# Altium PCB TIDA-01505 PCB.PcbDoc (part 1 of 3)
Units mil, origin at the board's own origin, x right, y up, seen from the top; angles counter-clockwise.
Board outline 7874.02 x 6929.13 mil, 2 copper layers (Top Layer, Bottom Layer), stack 62 mil thick; 307 components, 129 nets, 623 pads, 701 vias.
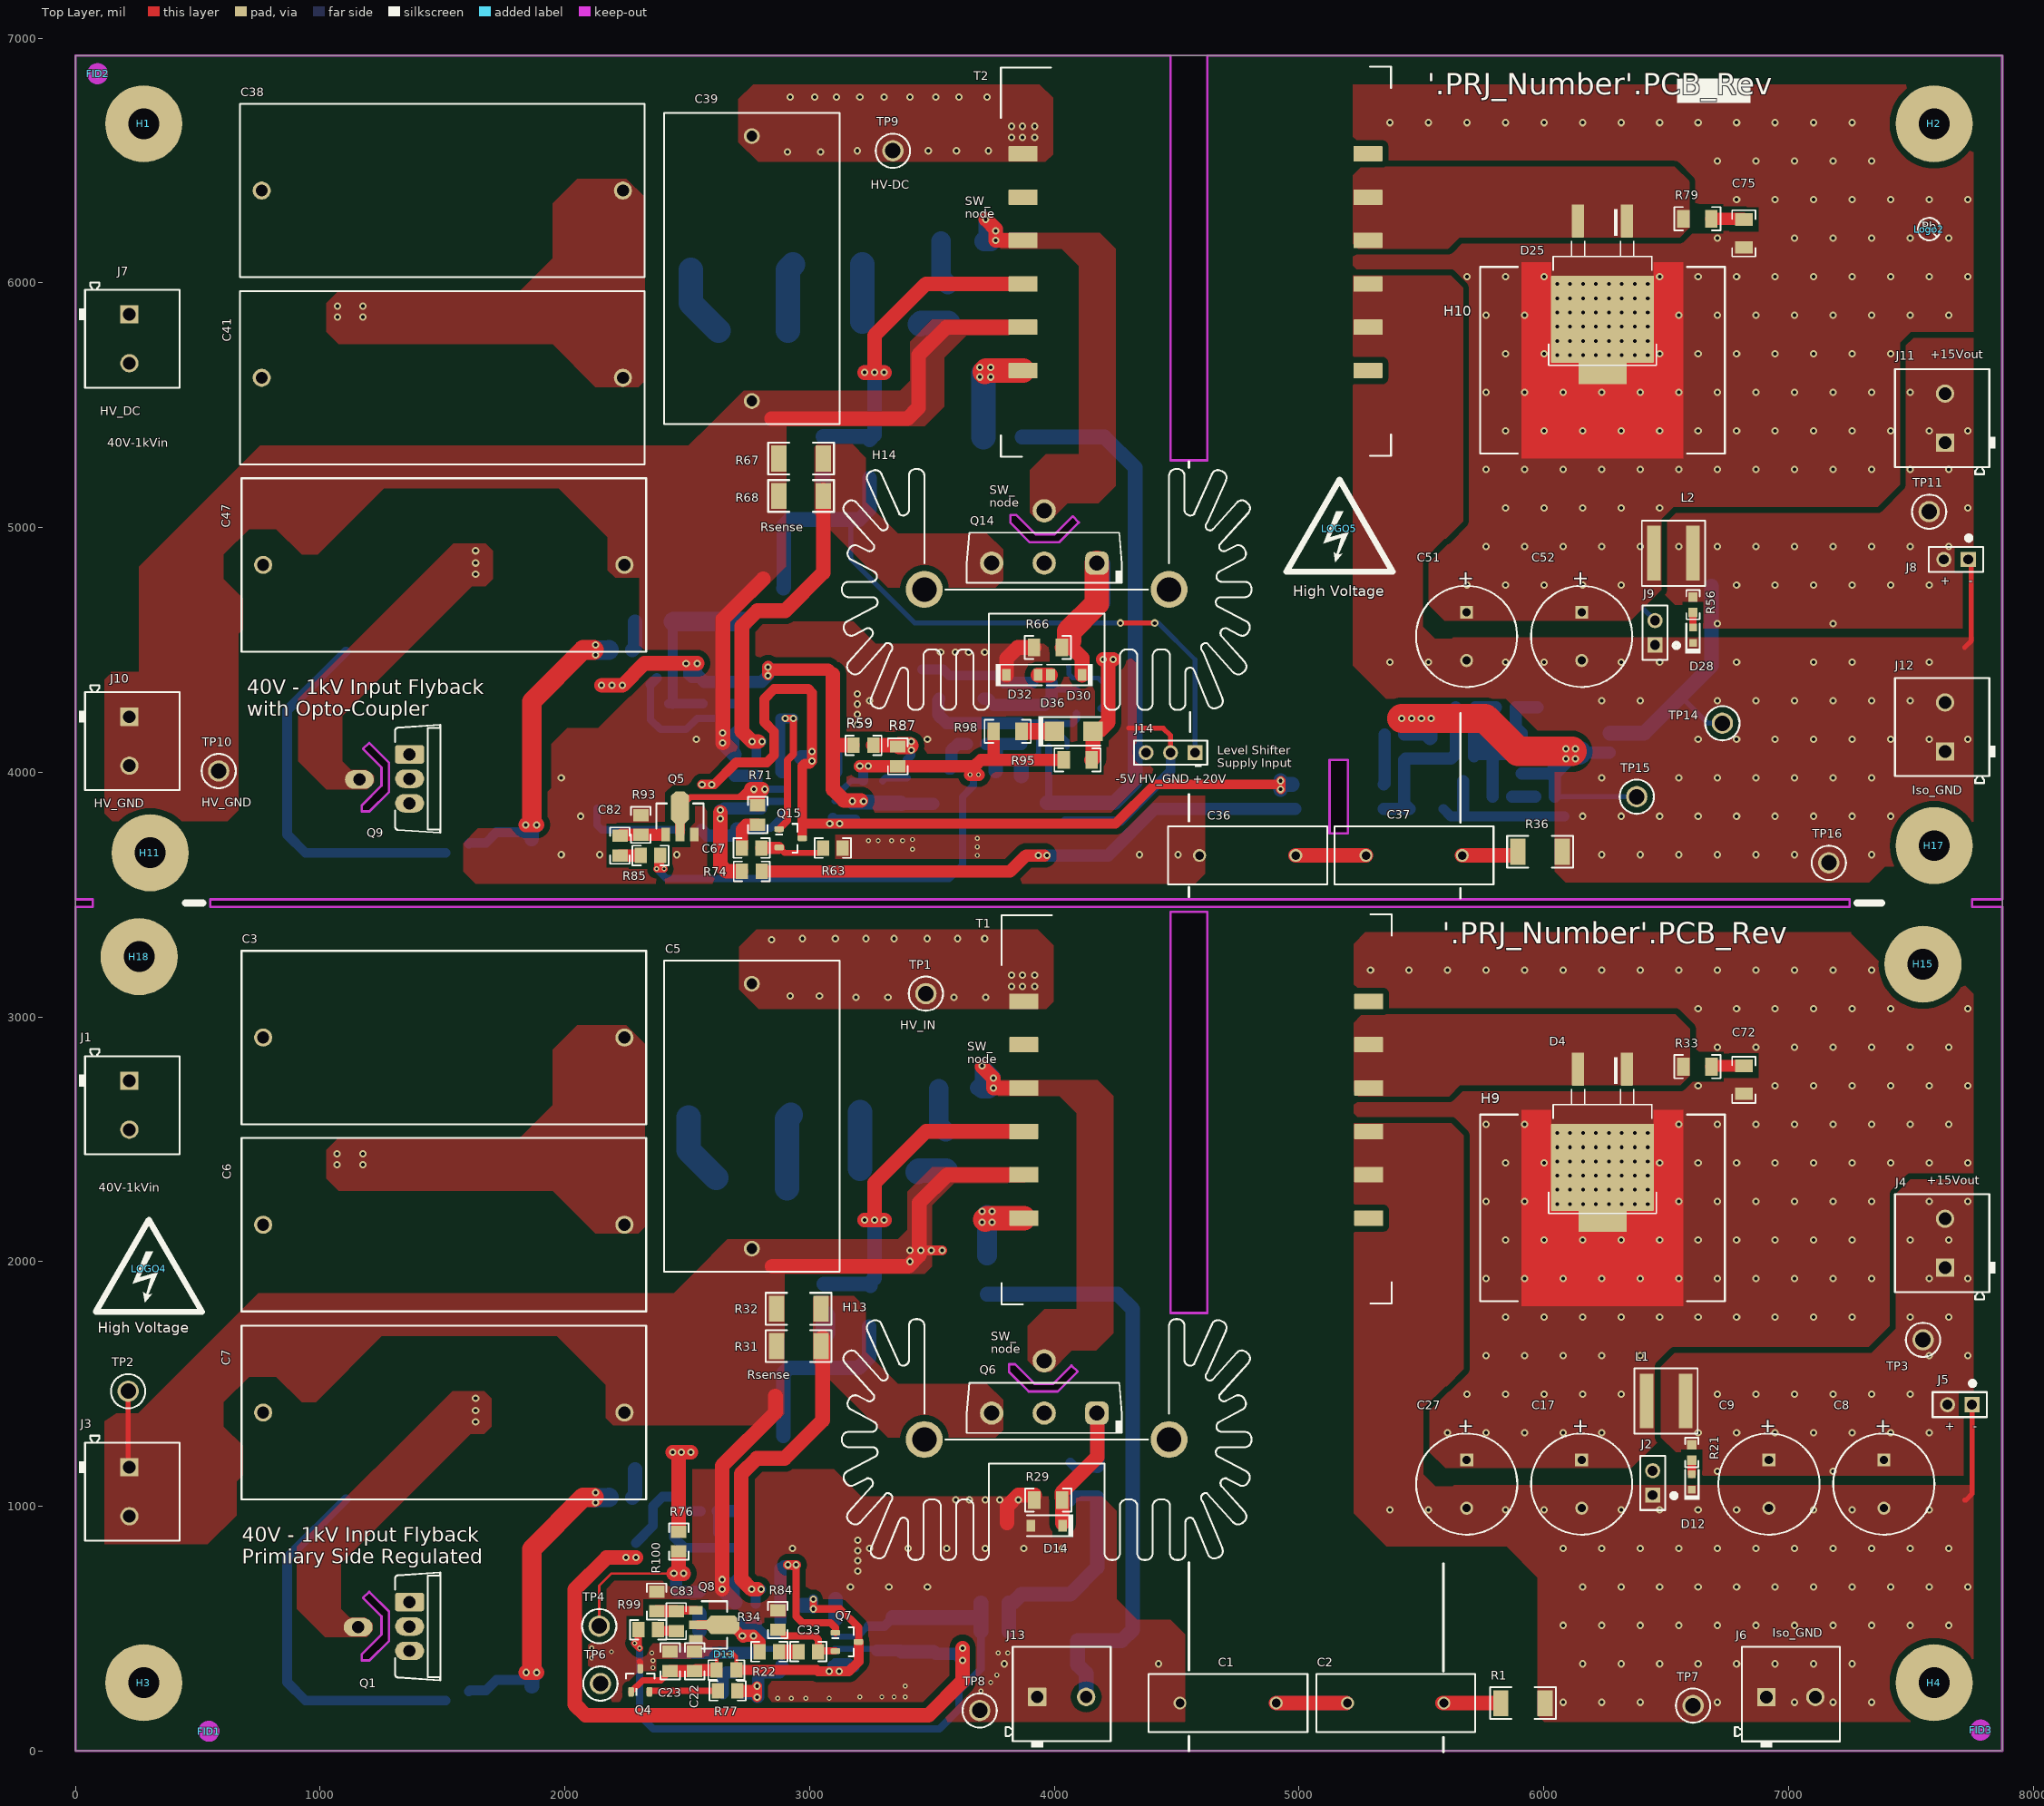
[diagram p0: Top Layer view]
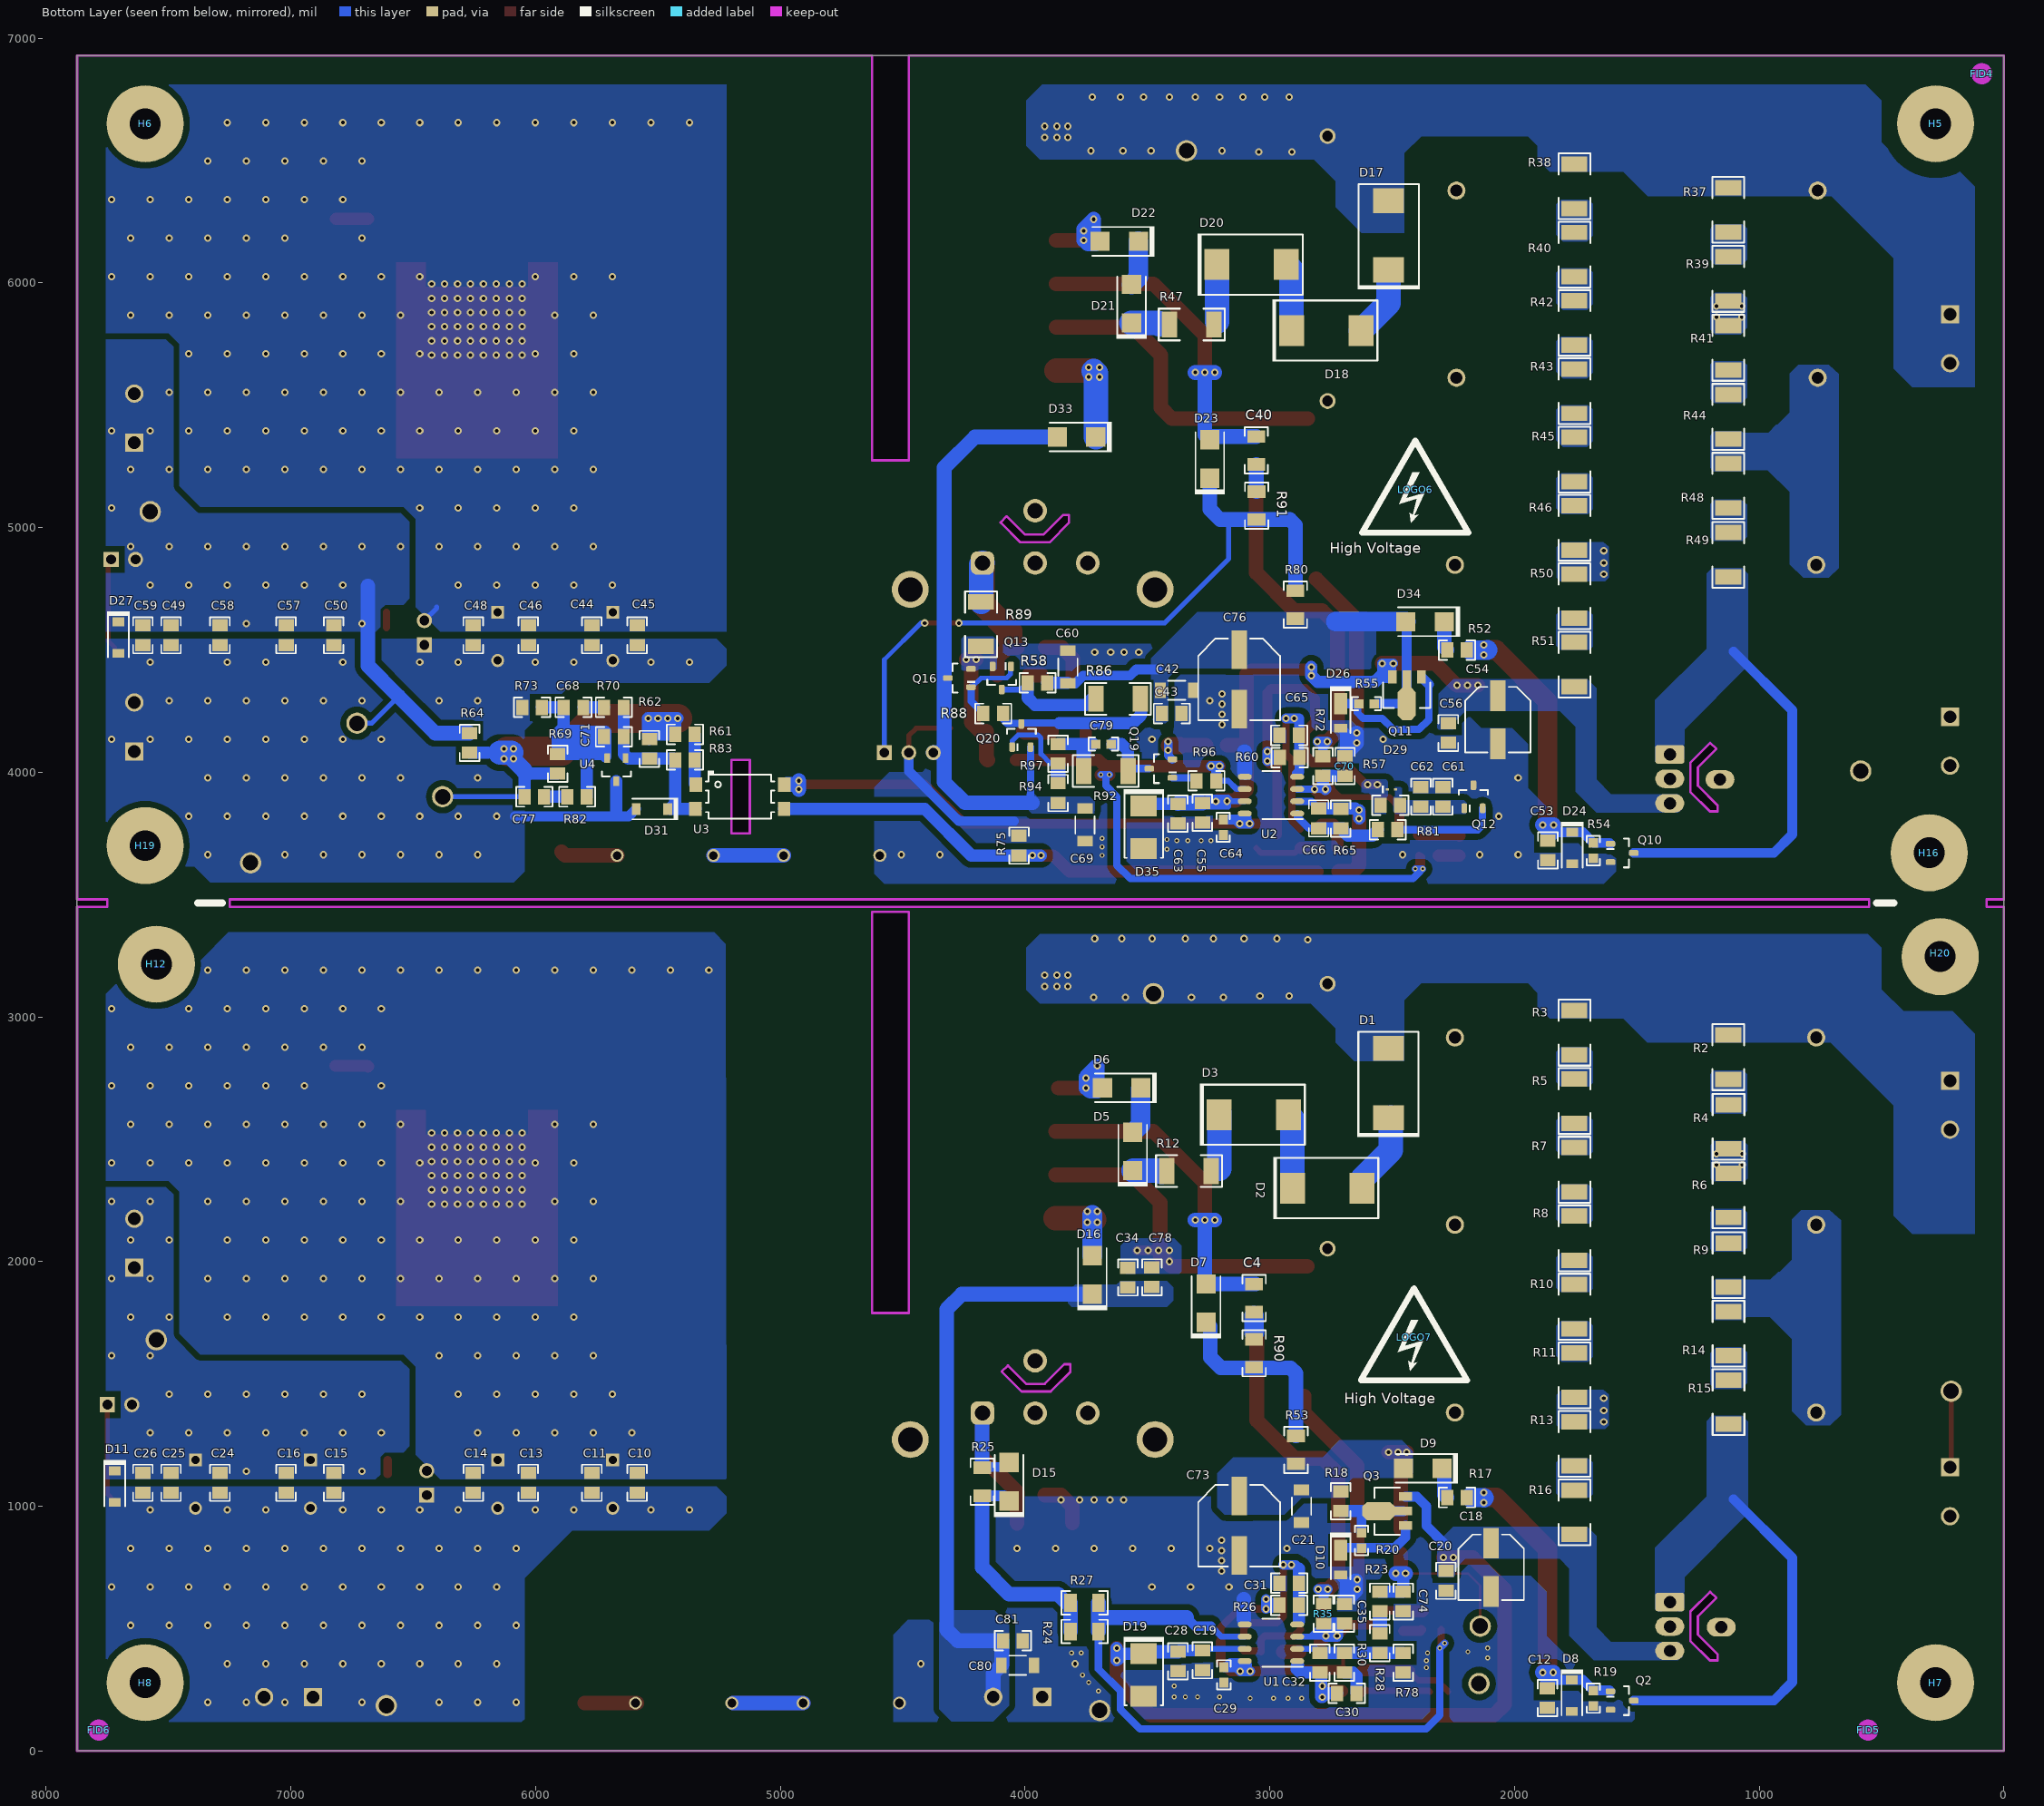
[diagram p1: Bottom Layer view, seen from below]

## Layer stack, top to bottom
Top Solder: solder mask 0.4, Solder Resist, Dk 3.5
Top Layer: signal copper 1.4
Dielectric1: core 59.2, FR-4, Dk 4.8
Bottom Layer: signal copper 1.4
Bottom Solder: solder mask 0.4, Solder Resist, Dk 3.5

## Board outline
0,0 7874.02,0 7874.02,6929.13 0,6929.13
cut-out: 7874.02,3480 7750,3480 7750,3450 7874.02,3450
cut-out: 0,3480 70,3480 70,3450 0,3450
cut-out: 550,3450 7250,3450 7250,3480 550,3480
cut-out: 1175,625 1200,650 1281.11,568.89 1281.11,450 1201.11,370 1170,370 1170,395 1250,475 1250,550
cut-out: 4475,1790 4625,1790 4625,3429.13 4475,3429.13
cut-out: 4475,5275 4625,5275 4625,6929.13 4475,6929.13
cut-out: 1175,4095 1200,4120 1281.11,4038.89 1281.11,3920 1201.11,3840 1170,3840 1170,3865 1250,3945 1250,4020
cut-out: 4075,5046.11 4100,5021.11 4018.89,4940 3900,4940 3820,5020 3820,5051.11 3845,5051.11 3925,4971.11 4000,4971.11
cut-out: 4070,1575 4095,1550 4013.89,1468.89 3895,1468.89 3815,1548.89 3815,1580 3840,1580 3920,1500 3995,1500
cut-out: 5125,4050 5200,4050 5200,3750 5125,3750

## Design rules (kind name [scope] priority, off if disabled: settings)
AcuteAngle [All] p1: minimum=3.00000000000000E+0001 checktracksonly=FALSE
AssemblyTestPointUsage [All] p1: valid=2
BoardOutlineClearance BoardOutlineClearance_MountingHoles [OnCopper and InComponentClass('Mounting Holes')] p1: gap=40 ignorepadtopadclearanceinfootprint=FALSE
BoardOutlineClearance BoardOutlineClearance_Poly_HV [OnCopper and IsPoly] p2: gap=118.11 ignorepadtopadclearanceinfootprint=FALSE
BoardOutlineClearance BoardOutlineClearance_Poly [OnCopper and IsPoly] p3: gap=25 ignorepadtopadclearanceinfootprint=FALSE
BoardOutlineClearance BoardOutlineClearance_overlay [Not OnTopSilkscreen and not OnBottomSilkscreen] p4: gap=0 ignorepadtopadclearanceinfootprint=FALSE
BoardOutlineClearance [OnCopper and Not InComponentClass('Logo') and not InComponentClass('FiducialMark') and not InRegion(1000,500,4000,800) and not InPoly] p5: gap=20 ignorepadtopadclearanceinfootprint=FALSE
Clearance Clearance_Poly_HV_to_HV [InNetClass('1500V')and InPolygon vs not ( InComponent('Q1') or InComponent('Q9') or IsKeepOut or IsBoardOutline or IsBoardCutoutRegion )and InPolygon] p1: gap=66.93 ignorepadtopadclearanceinfootprint=FALSE
Clearance Clearance_HV_Nets [InNetClass('1500V') vs Not InComponent('Q9') And  Not InComponent('J7') and not InComponent('J1')and not InComponent('Q1') and not InComponent('Q1') and not InComponent('Q9')and not IsKeepOut and not IsBoardOutline and not IsBoardCutoutRegion and not InNetClass('NC')] p2: gap=62.99 ignorepadtopadclearanceinfootprint=FALSE
Clearance Clearance_Keepouts [((IsTrack Or IsArc) And Not InPoly) And IsFree and IsKeepOut vs ((IsTrack Or IsArc) And Not InPoly) And IsFree and IsKeepOut] p3: gap=59.06 ignorepadtopadclearanceinfootprint=FALSE except(0: Arc-Hole Track-Hole SMDPad-Hole THPad-Hole Via-Hole Fill-Hole Poly-Hole Region-Hole Text-Hole)
Clearance Clearance_Poly [InPolygon] p4: gap=25 ignorepadtopadclearanceinfootprint=FALSE
Clearance [not InComponentClass('FiducialMark') and not InComponent('D15')] p5: gap=15 ignorepadtopadclearanceinfootprint=FALSE
ComponentClearance ComponentClearance_HStoFET [(InComponent('H14') OR InComponent('H13') OR InComponent('H3') OR InComponent('H10') OR InComponent('H9')) vs (InComponent('Q14') OR InComponent('D25') OR InComponent('Q6') OR InComponent('D4') OR InComponent('D25'))] p1: gap=0 collisioncheckmode=3 verticalgap=0 showdistances=FALSE
ComponentClearance ComponentClearance_MountingHoles_FiducialMarks [InComponentClass('Mounting Holes') vs InComponentClass('FiducialMark')] p2: gap=50 collisioncheckmode=3 verticalgap=10 showdistances=FALSE
ComponentClearance ComponentClearance_Shunt [InComponentClass('Header') vs InComponentClass('Shunt')] p3: gap=0 collisioncheckmode=3 verticalgap=0 showdistances=FALSE
ComponentClearance ComponentClearance_Logo [InComponentClass('Logo')] p4: gap=50 collisioncheckmode=3 verticalgap=10 showdistances=FALSE
ComponentClearance ComponentClearance_ScrewToNut [(HasFootprint('NY PMS 440 0025 PH')) vs (HasFootprint('Keystone_1902C'))] p5: gap=5 collisioncheckmode=3 verticalgap=10 showdistances=FALSE
ComponentClearance ComponentClearance_MountingHoles [InComponentClass('Mounting Holes')] p6: gap=250 collisioncheckmode=3 verticalgap=100000 showdistances=FALSE
ComponentClearance ComponentClearance_SmallPassives [HasFootprint('0201*') or HasFootprint('0402*') or HasFootprint('0508') or HasFootprint('0603*') or HasFootprint('0612') or HasFootprint('0805*') or HasFootprint('0815*') or HasFootprint('0830*') or HasFootprint('1206*') or HasFootprint('1210*') or HasFootprint('1808*') or HasFootprint('1812*') or HasFootprint('1825*') or HasFootprint('2010*') or HasFootprint('2220*') or HasFootprint('2225*') or HasFootprint('2512*') or HasFootprint('2728*') or HasFootprint('3518*') vs HasFootprint('0201*') or HasFootprint('0402*') or HasFootprint('0508') or HasFootprint('0603*') or HasFootprint('0612') or HasFootprint('0805*') or HasFootprint('0815*') or HasFootprint('0830*') or HasFootprint('1206*') or HasFootprint('1210*') or HasFootprint('1808*') or HasFootprint('1812*') or HasFootprint('1825*') or HasFootprint('2010*') or HasFootprint('2220*') or HasFootprint('2225*') or HasFootprint('2512*') or HasFootprint('2728*') or HasFootprint('3518*')] p7: gap=14.96 collisioncheckmode=3 verticalgap=10 showdistances=FALSE
ComponentClearance ComponentClearance_THtoSMT [IsThruComponent vs IsSMTComponent] p8: gap=40 collisioncheckmode=3 verticalgap=30 showdistances=FALSE
ComponentClearance ComponentClearance_THtoTH [IsThruComponent vs IsThruComponent] p9: gap=30 collisioncheckmode=3 verticalgap=30 showdistances=FALSE
ComponentClearance [All] p10: gap=10 collisioncheckmode=3 verticalgap=10 showdistances=FALSE
DiffPairsRouting [All] p1: maxlimit=100 minlimit=10 mostfreqgap=10 toplayer_minwidth=15 toplayer_maxwidth=15 toplayer_prefwidth=15 bottomlayer_minwidth=15 bottomlayer_maxwidth=15 bottomlayer_prefwidth=15 maxuncoupledlength=1000
FabricationTestPointUsage TestPointUsage [All] p1: valid=2 allowmultiple=FALSE
FabricationTestpoint Testpoint [All] p1: side=3 testpointundercomponent=TRUE minsize=40 maxsize=100 preferedsize=60 minholesize=0 maxholesize=40 preferedholesize=32 testpointgrid=1 allowsidetop=TRUE allowsidebottom=TRUE usegrid=TRUE gridtolerance=0.01
FanoutControl Fanout_LCC [IsLCC] p1: bgadir=Out bgaviamode=Centered fanoutstyle=Auto fanoutdirection=Alternating viagrid=1 // Fanout_LCC (Default Rule)
FanoutControl Fanout_BGA [IsBGA] p2: bgadir=Out bgaviamode=Centered fanoutstyle=Auto fanoutdirection=Alternating viagrid=1 // Fanout_BGA (Default Rule)
FanoutControl Fanout_Default [All] p4: bgadir=Out bgaviamode=Centered fanoutstyle=Auto fanoutdirection=Alternating viagrid=1 // Fanout_Default (Default Rule)
FanoutControl Fanout_Small [(CompPinCount < 5)] p5: bgadir=Out bgaviamode=Centered fanoutstyle=Auto fanoutdirection=OutThenIn viagrid=1 // Fanout_Small (Default Rule)
Height [All] p1: minheight=0 maxheight=1500 prefheight=500
HoleSize [All] p1: absolutevalues=TRUE maxlimit=251 minlimit=7.87 maxpercent=80.000 minpercent=20.000
MinimumAnnularRing MinimumAnnularRing_ThermalPadVias [IsVia and InAnyComponent] p1: minimumring=5.91
MinimumAnnularRing [All] p2: minimumring=5
MinimumSolderMaskSliver MinimumSolderMaskSliver_Logo [InComponentClass('Logo') vs InComponentClass('Logo')] p1: minsoldermaskwidth=0.7
MinimumSolderMaskSliver [All] p2: minsoldermaskwidth=1
NetAntennae [All] p1: netantennaetolerance=120
PlaneConnect [All] p1: planeconnectstyle=Relief reliefexpansion=10 reliefentries=4 reliefconductorwidth=10 reliefairgap=10
PolygonConnect [All] p1: connectstyle=Direct reliefconductorwidth=10 reliefentries=4 polygonreliefangle="90 Angle" airgapwidth=10
RoutingVias ThermalPadVias [IsVia and InAnyComponent] p1: holewidth=7.87 width=19.68 viastyle="Through Hole" minholewidth=7.87 minwidth=19.68 maxholewidth=12.99 maxwidth=23.62
RoutingVias [All] p2: holewidth=16 width=34 viastyle="Through Hole" minholewidth=7.87 minwidth=20 maxholewidth=40 maxwidth=65
SilkToBoardRegionClearance [Not ((IsComment or IsDesignator) And (Hide <> 'False')) and not InRegion(1000,500,4000,800)] p1:
SilkToSilkClearance SilkToSilkClearance_Pb-FreeLogo [(HasFootprint('Pb-Free_Overlay_Medium') OR HasFootprint('Pb-Free_Overlay_Small')) vs (HasFootprint('Pb-Free_Overlay_Medium') OR HasFootprint('Pb-Free_Overlay_Small'))] p1: silktosilkclearance=0
SilkToSilkClearance [All] p2: silktosilkclearance=4
SilkToSolderMaskClearance SilkToComponentPadClearance [(IsPad or IsFill or IsRegion) and InAnycomponent] p1: minsilkscreentomaskgap=0 clearancetoexposedcopper=TRUE
SilkToSolderMaskClearance "Silk to Solder Mask Opening" [All] p2: minsilkscreentomaskgap=0 clearancetoexposedcopper=FALSE
SolderMaskExpansion [All] p1: expansion=1.97
Width [All] p1: maxlimit=500 minlimit=6 preferedwidth=10 minimp=50.000000 maximp=50.000000 favimp=50.000000 checkconnectedcopper=TRUE
13 further rules are at their usual default settings.

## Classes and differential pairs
net class 1500V: HV_DC HV_IN_PSR NetC3_2 NetC6_2 NetC38_2 NetC41_2 NetD1_1 NetD2_1 NetD3_1 NetD5_1 NetD5_2 NetD17_1 NetD18_1 NetD20_1 NetD21_1 NetD21_2 NetQ1_2 NetQ9_2 NetR2_1 NetR3_1 NetR5_1 NetR6_1 NetR7_1 NetR8_1 NetR10_1 NetR37_1 NetR38_1 NetR40_1 NetR41_1 NetR42_1 NetR43_1 NetR45_1 SW_node SW_PSR
component class Flyback_withOpto: C36 C37 C38 C39 C40 C41 C42 C43 C44 C45 C46 C47 C48 C49 C50 C51 C52 C53 C54 C55 C56 C57 C58 C59 C60 C61 C62 C63 C64 C65 C66 C67 C68 C69 C70 C71 C75 C76 C77 C79 C82 D17 D18 D20 D21 D22 D23 D24 D25 D26 D27 D28 D29 D30 D31 D32 D33 D34 D35 D36 H10 H14 J7 J8 J9 J10 J11 J12 J14 L2 Q5 Q9 Q10 Q11 Q12 Q13 Q14 Q15 Q16 Q19 Q20 R36 R37 R38 R39 R40 R41 R42 R43 R44 R45 R46 R47 R48 R49 R50 R51 R52 R54 R55 R56 R57 R58 R59 R60 R61 R62 R63 R64 R65 R66 R67 R68 R69 R70 R71 R72 R73 R74 R75 R79 R80 R81 R82 R83 R85 R86 R87 R88 R89 R91 R92 R93 R94 R95 R96 R97 R98 T2 TP9 TP10 TP11 TP14 TP15 TP16 U2 U3 U4
component class Flyback_PSR: C1 C2 C3 C4 C5 C6 C7 C8 C9 C10 C11 C12 C13 C14 C15 C16 C17 C18 C19 C20 C21 C22 C23 C24 C25 C26 C27 C28 C29 C30 C31 C32 C33 C34 C35 C72 C73 C74 C78 C80 C81 C83 D1 D2 D3 D4 D5 D6 D7 D8 D9 D10 D11 D12 D13 D14 D15 D16 D19 H9 H13 J1 J2 J3 J4 J5 J6 J13 L1 Q1 Q2 Q3 Q4 Q6 Q7 Q8 R1 R2 R3 R4 R5 R6 R7 R8 R9 R10 R11 R12 R13 R14 R15 R16 R17 R18 R19 R20 R21 R22 R23 R24 R25 R26 R27 R28 R29 R30 R31 R32 R33 R34 R35 R53 R76 R77 R78 R84 R90 R99 R100 T1 TP1 TP2 TP3 TP4 TP6 TP7 TP8 U1
component class "Mounting Holes": H1 H2 H3 H4 H11 H15 H17 H18
component class Hardware: FID1 FID2 FID3 FID4 FID5 FID6 H1 H2 H3 H4 H5 H6 H7 H8 H11 H12 H15 H16 H17 H18 H19 H20 Logo2 LOGO4 LOGO5 LOGO6 LOGO7 ZZ1 ZZ2 ZZ3 ZZ4
component class FiducialMark: FID1 FID2 FID3 FID4 FID5 FID6
component class AssemblyNote: ZZ1 ZZ2 ZZ3 ZZ4

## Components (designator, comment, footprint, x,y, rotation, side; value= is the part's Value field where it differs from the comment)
C1 "CK45-R3FD222K-NRA" CK45-RR_1650x600 4710,195.43 r180 top value=2200pF
C2 "CK45-R3FD222K-NRA" CK45-RR_1650x600 5395,195.43 r180 top value=2200pF
C3 "B32776P6106K000" B32776P_4200x1800x3250 1505,2915.43 r0 top value=10uF
C4 "GRM31B5C2J102JW01L" 1206 3063.78,1850.39 r270 bottom value=1000pF
C5 "R76TR32204030J" Kemet_3200x1800x3300 2763.74,2594.09 r270 top value=0.22uF
C6 "B32776P6106K000" B32776P_4200x1800x3250 1505,2150.43 r180 top value=10uF
C7 "B32776P6106K000" B32776P_4200x1800x3250 1505,1382.76 r0 top value=10uF
C8 "EKZE350ELL471MJ20S" Chemi-Con_1000x2000 7390,1090.43 r270 top value=470uF
C9 "EKZE350ELL471MJ20S" Chemi-Con_1000x2000 6920,1090.43 r270 top value=470uF
C10 "GRM21BR6YA106KE43L" 0805_HV 5585,1095.43 r270 bottom value=10uF
C11 "GRM21BR6YA106KE43L" 0805_HV 5770,1095.43 r270 bottom value=10uF
C12 "GRM21BR71H224KA01L" 0805_HV 1865,215.43 r270 bottom value=0.22uF
C13 "GRM21BR6YA106KE43L" 0805_HV 6030,1095.43 r270 bottom value=10uF
C14 "GRM21BR6YA106KE43L" 0805_HV 6255,1095.43 r270 bottom value=10uF
C15 "GRM21BR6YA106KE43L" 0805_HV 6825,1095.43 r270 bottom value=10uF
C16 "GRM21BR6YA106KE43L" 0805_HV 7020,1095.43 r270 bottom value=10uF
C17 "EKZE350ELL471MJ20S" Chemi-Con_1000x2000 6155,1090.43 r270 top value=470uF
C18 "EEE-FK1H220P" SM_RADIAL_D 2095,750.43 r270 bottom value=22uF
C19 "C2012X7R1H104K085AA" 0805_HV 3275,370.43 r270 bottom value=0.1uF
C20 "CGA4J3X7R1H225K125AB" 0805_HV 2280,695 r270 bottom value=2.2uF
C21 "GRM31CR72A105KA01L" 1206_180 2870,1000 r270 bottom value=1uF
C22 "GRM21BR71E105KA99L" 0805_HV 2530,365.43 r270 top value=1uF
C23 "GRM21BR71E105KA99L" 0805_HV 2430,365.43 r270 top value=1uF
C24 "GRM21BR6YA106KE43L" 0805_HV 7290,1095.43 r270 bottom value=10uF
C25 "GRM21BR6YA106KE43L" 0805_HV 7490,1095.43 r270 bottom value=10uF
C26 "C2012X7R1H104K085AA" 0805_HV 7605,1095.43 r270 bottom value=0.1uF
C27 "EKZE350ELL471MJ20S" Chemi-Con_1000x2000 5685,1090.43 r270 top value=470uF
C28 "C2012X7R1H104K085AA" 0805_HV 3375,365.43 r270 bottom value=0.1uF
C29 "GRM188R71E105KA12D" 0603 3187.56,310.43 r270 bottom value=1uF
C30 "GRM21BR71E334KA01L" 0805_HV 2685,235 r180 bottom value=0.33uF
C31 "GCM2165C1H102JA16D" 0805_HV 2920,685.43 r0 bottom value=1000pF
C32 "GRM216R71E561KA01D" 0805_HV 2795,360.43 r90 bottom value=560pF
C33 "GRM216R71H103KA01D" 0805_HV 2995,405.43 r180 top value=0.01uF
C34 "GRM21BR6YA106KE43L" 0805_HV 3580,1935 r90 bottom value=10uF
C35 "GRM2165C1H221JA01D" 0805_HV 2695,560.43 r90 bottom value=220pF
C36 "CK45-R3FD222K-NRA" CK45-RR_1650x600 4790,3660 r180 top value=2200pF
C37 "CK45-R3FD222K-NRA" CK45-RR_1650x600 5470,3660 r180 top value=2200pF
C38 "B32776P6106K000" B32776P_4200x1800x3250 1498.74,6377.32 r0 top value=10uF
C39 "R76TR32204030J" Kemet_3200x1800x3300 2763.74,6058.66 r270 top value=0.22uF
C40 "GRM31B5C2J102JW01L" 1206 3055,5314.96 r270 bottom value=1000pF
C41 "B32776P6106K000" B32776P_4200x1800x3250 1498.74,5612.32 r180 top value=10uF
C42 "GRM31CR72A105KA01L" 1206_180 3380,4335 r180 bottom value=1uF
C43 "GRM21BR72A103KA01L" 0805_HV 3400,4240 r180 bottom value=0.01uF
C44 "GRM21BR6YA106KE43L" 0805_HV 5770.16,4560 r270 bottom value=10uF
C45 "GRM21BR6YA106KE43L" 0805_HV 5585.16,4560 r270 bottom value=10uF
C46 "GRM21BR6YA106KE43L" 0805_HV 6030.16,4560 r270 bottom value=10uF
C47 "B32776P6106K000" B32776P_4200x1800x3250 1505,4847.32 r0 top value=10uF
C48 "GRM21BR6YA106KE43L" 0805_HV 6255.12,4560 r270 bottom value=10uF
C49 "GRM21BR6YA106KE43L" 0805_HV 7490,4560 r270 bottom value=10uF
C50 "GRM21BR6YA106KE43L" 0805_HV 6825,4560 r270 bottom value=10uF
C51 "EKZE350ELL471MJ20S" Chemi-Con_1000x2000 5684.71,4555 r270 top value=470uF
C52 "EKZE350ELL471MJ20S" Chemi-Con_1000x2000 6155.12,4555 r270 top value=470uF
C53 "GRM21BR71H224KA01L" 0805_HV 1863.73,3679.96 r270 bottom value=0.22uF
C54 "EEE-FK1H220P" SM_RADIAL_D 2067.56,4214.96 r270 bottom value=22uF
C55 "C2012X7R1H104K085AA" 0805_HV 3275.08,3834.33 r270 bottom value=0.1uF
C56 "CGA4J3X7R1H225K125AB" 0805_HV 2270,4160 r270 bottom value=2.2uF
C57 "GRM21BR6YA106KE43L" 0805_HV 7020,4560 r270 bottom value=10uF
C58 "GRM21BR6YA106KE43L" 0805_HV 7290,4560 r270 bottom value=10uF
C59 "C2012X7R1H104K085AA" 0805_HV 7605,4560 r270 bottom value=0.1uF
C60 "GRM31CR72A105KA01L" 1206_180 3825,4430 r90 bottom value=1uF
C61 "GRM21BR71E105KA99L" 0805_HV 2292.56,3899.96 r270 bottom value=1uF
C62 "GRM21BR71E105KA99L" 0805_HV 2382.56,3899.96 r270 bottom value=1uF
C63 "C2012X7R1H104K085AA" 0805_HV 3375.08,3831.22 r270 bottom value=0.1uF
C64 "GRM188R71E105KA12D" 0603 3190,3775 r270 bottom value=1uF
C65 "GCM2165C1H102JA16D" 0805_HV 2920.08,4151.22 r0 bottom value=1000pF
C66 "GRM2165C1H332JA01D" 0805_HV 2800.08,3811.22 r90 bottom value=3300pF
C67 "GRM216R71H103KA01D" 0805_HV 2762.56,3689.96 r180 top value=0.01uF
C68 "GRM21BR71H224KA01L" 0805_HV 5845,4265 r180 bottom value=0.22uF
C69 "GRM31CR72A105KA01L" 1206_180 3755,3785 r270 bottom value=1uF
C70 "GRM2165C1H221JA01D" 0805_HV 2692.56,4024.96 r90 bottom value=220pF
C71 "GRM219R71H334KA88D" 0805_HV 5680,4145 r180 bottom value=0.33uF
C72 "GRM31B5C2J102JW01L" 1206 6817.52,2742.87 r90 top value=1000pF
C73 "EEE-2AA100UP" SM_RADIAL_E 3125,920.43 r270 bottom value=10uF
C74 "GRM2165C2A621JA01D" 0805_HV 2454.41,610 r270 bottom value=620pF
C75 "GRM31B5C2J102JW01L" 1206 6817.52,6202.44 r90 top value=1000pF
C76 "EEE-2AA100UP" SM_RADIAL_E 3125.08,4379.33 r270 bottom value=10uF
C77 "GCM21BR71H104KA37K" 0805_HV 6005.31,3899.37 r180 bottom value=0.1uF
C78 "GRM21BR6YA106KE43L" 0805_HV 3481.46,1935.43 r90 bottom value=10uF
C79 "GRM1885C1H101JA01D" 0603 3680,4115 r0 bottom value=100pF
C80 "GRM31CR72A105KA01L" 1206_180 4030,350 r180 bottom value=1uF
C81 "GRM21BR6YA106KE43L" 0805_HV 4050,450 r180 bottom value=10uF
C82 "GRM2165C1H151JA01D" 0805_HV 2225,3700 r90 top value=150pF
C83 "GRM2165C1H151JA01D" 0805_HV 2455,530 r90 top value=150pF
D1 "SMCJ110A" SMC_265 2515,2730 r90 bottom value=110V
D2 "SMCJ110A" SMC_265 2765,2300 r180 bottom value=110V
D3 "SMCJ110A" SMC_265 3065,2600 r180 bottom value=110V
D4 "VS-20CTQ150SPBF" DDPAK 6240,2540.43 r270 top value=150V
D5 "US1M-13-F" SMA 3560,2450 r90 bottom value=1000V
D6 "US1M-13-F" SMA 3605,2710 r0 bottom value=1000V
D7 "ES1F" SMA 3260,1830 r90 bottom value=300V
D8 "MMSZ4705T1G" SOD-123 1765,225.43 r270 bottom value=18V
D9 "ES1F" SMA 2375,1155 r0 bottom value=300V
D10 "DFLZ18-7" PowerDI123 2710,770 r270 bottom value=18V
D11 "MMSZ5248B-7-F" SOD-123 7720,1080.43 r270 bottom value=18V
D12 "150060GS75000" WL-SMCW_GREEN 6605,1100 r90 top value=Green
D13 "RB520CM-60T2R" SOD-923 2650,395.43 r180 top value=60V
D14 "MMSZ5251B-7-F" SOD-123 3968.78,920.43 r180 top value=22V
D15 "B170-13-F" SMA 4065,1100 r90 bottom value=70V
D16 "ES1F" SMA 3725,1945 r90 bottom value=300V
D17 "SMCJ110A" SMC_265 2513.74,6194.96 r90 bottom value=110V
D18 "SMCJ110A" SMC_265 2768.74,5804.96 r180 bottom value=110V
D19 "SMBJ18A-13-F" SMB 3515,310.43 r270 bottom value=18V
D20 "SMCJ110A" SMC_265 3073.74,6074.96 r180 bottom value=110V
D21 "US1M-13-F" SMA 3565,5915 r90 bottom value=1000V
D22 "US1M-13-F" SMA 3615,6170 r0 bottom value=1000V
D23 "ES1F" SMA 3245,5280 r90 bottom value=300V
D24 "MMSZ4705T1G" SOD-123 1764.22,3689.96 r270 bottom value=18V
D25 "VS-20CTQ150SPBF" DDPAK 6240,6007.13 r270 top value=150V
D26 "DFLZ16-7" PowerDI123 2710,4230 r270 bottom value=16V
D27 "MMSZ5248B-7-F" SOD-123 7705,4550 r270 bottom value=18V
D28 "150060GS75000" WL-SMCW_GREEN 6610,4560 r90 top value=Green
D29 "RB520CM-60T2R" SOD-923 2502.56,3929.96 r180 bottom value=60V
D30 "MMSZ5251B-7-F" SOD-123 4048.78,4397.09 r180 top value=22V
D31 "BZT52C11-7-F" SOD-123 5525,3850 r0 bottom value=11V
D32 "MMSZ5232B-7-F" SOD-123 3868.78,4397.09 r0 top value=5.6V
D33 "ES1F" SMA 3789.45,5370 r0 bottom value=300V
D34 "ES1F" SMA 2365,4615 r0 bottom value=300V
D35 "SMBJ18A-13-F" SMB 3515,3775 r270 bottom value=18V
D36 "B170-13-F" SMA 4079.37,4167.26 r0 top value=70V
FID1 "Fiducial" Fiducial10-20 545,80 r90 top
FID2 "Fiducial" Fiducial10-20 90,6855 r90 top
FID3 "Fiducial" Fiducial10-20 7785,85 r90 top
FID4 "Fiducial" Fiducial10-20 90,6855 r90 bottom
FID5 "Fiducial" Fiducial10-20 555,85 r90 bottom
FID6 "Fiducial" Fiducial10-20 7785,85 r90 bottom
H1 "NY PMS 440 0025 PH" "NY PMS 440 0025 PH" 278.74,6650.39 r0 top locked
H2 "NY PMS 440 0025 PH" "NY PMS 440 0025 PH" 7595.28,6650.39 r0 top locked
H3 "NY PMS 440 0025 PH" "NY PMS 440 0025 PH" 278.74,278.74 r0 top locked
H4 "NY PMS 440 0025 PH" "NY PMS 440 0025 PH" 7595.28,278.74 r0 top locked
H5 "1902C" Keystone_1902C 278.74,6650.39 r180 bottom locked
H6 "1902C" Keystone_1902C 7595.28,6650.39 r180 bottom locked
H7 "1902C" Keystone_1902C 278.74,278.74 r180 bottom locked
H8 "1902C" Keystone_1902C 7595.28,278.74 r180 bottom locked
H9 "7109DG" Aavid_7109DG 6240,2219.13 r180 top
H10 "7109DG" Aavid_7109DG 6240,5683.7 r180 top
H11 "NY PMS 440 0025 PH" "NY PMS 440 0025 PH" 304.82,3670.49 r0 top
H12 "1902C" Keystone_1902C 7550.55,3215.98 r180 bottom
H13 "RA-T2X-25E" HSINK_RA-T2X-25E 3968.78,1272.52 r180 top
H14 "RA-T2X-25E" HSINK_RA-T2X-25E 3968.78,4747.09 r180 top
H15 "NY PMS 440 0025 PH" "NY PMS 440 0025 PH" 7550.01,3215.49 r0 top
H16 "1902C" Keystone_1902C 305,3670 r180 bottom
H17 "NY PMS 440 0025 PH" "NY PMS 440 0025 PH" 7595.52,3700 r0 top
H18 "NY PMS 440 0025 PH" "NY PMS 440 0025 PH" 259.82,3246 r0 top
H19 "1902C" Keystone_1902C 7595,3700 r180 bottom
H20 "1902C" Keystone_1902C 260,3260 r180 bottom
J1 "1715721" PhoenixContact_1715721 220,2639.13 r270 top
J2 "PPTC021LFBN-RC" CONN_PPTC021LFBN-RC 6445,1095 r270 top
J3 "1715721" PhoenixContact_1715721 220,1059.13 r270 top
J4 "1715721" PhoenixContact_1715721 7640,2075 r90 top
J5 "PPTC021LFBN-RC" CONN_PPTC021LFBN-RC 7700,1415 r0 top
J6 "1715721" PhoenixContact_1715721 7010,220 r0 top
J7 "1715721" PhoenixContact_1715721 220,5771.6 r270 top
J8 "PPTC021LFBN-RC" CONN_PPTC021LFBN-RC 7685,4870 r0 top
J9 "PPTC021LFBN-RC" CONN_PPTC021LFBN-RC 6455,4570 r270 top
J10 "1715721" PhoenixContact_1715721 220,4126.77 r270 top
J11 "1715721" PhoenixContact_1715721 7640,5447.48 r90 top
J12 "1715721" PhoenixContact_1715721 7640,4185 r90 top
J13 "1715721" PhoenixContact_1715721 4030,220.43 r0 top
J14 "HTSW-103-09-G-S" Samtec_HTSW-103-09-x-S 4475,4080 r180 top
L1 "XAL6030-222MEB" XAL6030 6500,1430 r180 top value=2.2uH
L2 "XAL6030-222MEB" XAL6030 6530,4895 r180 top value=2.2uH
Logo2 "Pb-Free Symbol" Pb-Free_Overlay_Small 7575,6220 r0 top
LOGO4 "DANGER HIGH VOLTAGE" IEC_HighVoltage_Medium 300,1970 r0 top
LOGO5 "DANGER HIGH VOLTAGE" IEC_HighVoltage_Medium 5165,4995 r0 top
LOGO6 "DANGER HIGH VOLTAGE" IEC_HighVoltage_Medium 2405,5155 r180 bottom
LOGO7 "DANGER HIGH VOLTAGE" IEC_HighVoltage_Medium 2410,1690 r180 bottom
Q1 "STP03D200" TO-220AB 1364.96,508.6 r270 top value="1200 V"
Q2 "2N7002-7-F" SOT-23 1559.96,205.39 r180 bottom value=60V
Q3 "PBSS4250X,115" SOT-89-3 2520,980 r0 bottom value="50 V"
Q4 "MMBT2907ALT1G" SOT-23 2307.85,288.43 r90 top value="60 V"
Q5 "DXT2222A-13" SOT-89-3 2470,3820 r90 top value="40 V"
Q6 "C2M1000170D" TO-247 3958.78,1380.39 r180 top value=1700V
Q7 "MMBT3904-7-F" SOT-23 3152.56,445.39 r0 top value="40 V"
Q8 "DXT2222A-13" SOT-89-3 2610,515 r0 top value="40 V"
Q9 "STP03D200" TO-220AB 1364.96,3973.16 r270 top value="1200 V"
Q10 "2N7002-7-F" SOT-23 1559.96,3669.96 r180 bottom value=60V
Q11 "PBSS4250X,115" SOT-89-3 2440,4315 r270 bottom value="50 V"
Q12 "MMBT2907ALT1G" SOT-23 2167.56,3899.96 r90 bottom value="60 V"
Q13 "BC817-16LT1G" SOT-23 4095,4385 r270 bottom value="45 V"
Q14 "C2M1000170D" TO-247 3958.78,4854.96 r180 top value=1700V
Q15 "MMBT3904-7-F" SOT-23 2922.56,3729.96 r0 top value="40 V"
Q16 "BC807-40LT1G" SOT-23 4267.99,4385 r0 bottom value="45 V"
Q19 "BSS84-7-F" SOT-23 3445,4015 r0 bottom value=-50V
Q20 "2N7002K-T1-E3" SOT-23 4015.12,4150 r90 bottom value=60V
R1 "CRCW20100000Z0EF" 2010 5915,195 r0 top value=0
R2 "ERJ12ZYJ155U" 2010 1126.22,2835.43 r90 bottom value=1.5Meg
R3 "CRCW201049K9FKEF" 2010 1755,2935.51 r90 bottom value=49.9k
R4 "ERJ12ZYJ155U" 2010 1125,2550.43 r90 bottom value=1.5Meg
R5 "CRCW201049K9FKEF" 2010 1755,2655.44 r90 bottom value=49.9k
R6 "ERJ12ZYJ155U" 2010 1125,2270.43 r90 bottom value=1.5Meg
R7 "CRCW201049K9FKEF" 2010 1755,2375.36 r90 bottom value=49.9k
R8 "CRCW201049K9FKEF" 2010 1755,2095.29 r90 bottom value=49.9k
R9 "ERJ12ZYJ155U" 2010 1125,1985 r90 bottom value=1.5Meg
R10 "CRCW201049K9FKEF" 2010 1755,1815.22 r90 bottom value=49.9k
R11 "CRCW201049K9FKEF" 2010 1755,1535.15 r90 bottom value=49.9k
R12 "CRCW201033R0JNEF" 2010 3330,2370 r0 bottom value=33
R13 "CRCW20101M00FKEF" 2010 1755,1255.07 r90 bottom value=1.00Meg
R14 "ERJ12ZYJ155U" 2010 1125,1705.43 r90 bottom value=1.5Meg
R15 "ERJ12ZYJ155U" 2010 1125,1425.43 r90 bottom value=1.5Meg
R16 "CRCW20101M00FKEF" 2010 1755,975 r90 bottom value=1.00Meg
R17 "CRCW08052K00FKEA" 0805_HV 2235,1035.43 r0 bottom value=2.00k
R18 "CRCW080510R0FKEA" 0805_HV 2710,1020.43 r90 bottom value=10.0
R19 "CRCW0603499KFKEA" 0603 1677.44,215.39 r90 bottom value=499k
R20 "CRCW06034K70JNEA" 0603 2625,860 r90 bottom value=4.7k
R21 "CRCW060310K0FKEA" 0603 6605,1220 r90 top value=10.0k
R22 "CRCW080520K0FKEA" 0805_HV 2660,330.43 r180 top value=20.0k
R23 "CRCW080549R9FKEA" 0805_HV 2550,610 r90 bottom value=49.9
R24 "CRCW120610R0FKEA" 1206 3757,487.75 r0 bottom value=10.0
R25 "CRCW120610R0FKEA" 1206 4175,1100 r90 bottom value=10.0
R26 "CRCW080513K0FKEA" 0805_HV 2920,595.43 r0 bottom value=13.0k
R27 "CRCW120610R0FKEA" 1206 3757,605 r0 bottom value=10.0
R28 "CRCW080520K5FKEA" 0805_HV 2550,440 r90 bottom value=20.5k
R29 "CRCW120610K0FKEA" 1206 3975,1025 r0 top value=10.0k
R30 "CRCW080520K5FKEA" 0805_HV 2695,360.43 r270 bottom value=20.5k
R31 "CRM2010-FX-R910ELF" 2010 2955.16,1654.27 r0 top value=0.91
R32 "CRM2010-FX-R910ELF" 2010 2955.16,1807.04 r0 top value=0.91
R33 "CRCW1206100RFKEA" 1206 6628,2796.43 r0 top value=100
R34 "CRCW08059K09FKEA" 0805_HV 2835,405 r180 top value=9.09k
R35 "CRCW08052K20JNEA" 0805_HV 2780,560.43 r90 bottom value=2.2k
R36 "CRCW20100000Z0EF" 2010 5985,3675 r0 top value=0
R37 "ERJ12ZYJ155U" 2010 1126.22,6298.58 r90 bottom value=1.5Meg
R38 "CRCW201049K9FKEF" 2010 1755,6395 r90 bottom value=49.9k
R39 "ERJ12ZYJ155U" 2010 1126.22,6016.58 r90 bottom value=1.5Meg
R40 "CRCW201049K9FKEF" 2010 1755,6115.71 r90 bottom value=49.9k
R41 "ERJ12ZYJ155U" 2010 1126.22,5734.58 r90 bottom value=1.5Meg
R42 "CRCW201049K9FKEF" 2010 1755,5836.43 r90 bottom value=49.9k
R43 "CRCW201049K9FKEF" 2010 1755,5557.14 r90 bottom value=49.9k
R44 "ERJ12ZYJ155U" 2010 1126.22,5452.58 r90 bottom value=1.5Meg
R45 "CRCW201049K9FKEF" 2010 1755,5277.86 r90 bottom value=49.9k
R46 "CRCW201049K9FKEF" 2010 1755,4998.57 r90 bottom value=49.9k
R47 "CRCW201033R0JNEF" 2010 3318.74,5829.96 r0 bottom value=33
R48 "ERJ12ZYJ155U" 2010 1126.22,5170.58 r90 bottom value=1.5Meg
R49 "ERJ12ZYJ155U" 2010 1126.22,4888.58 r90 bottom value=1.5Meg
R50 "CRCW20101M00FKEF" 2010 1755,4719.29 r90 bottom value=1.00Meg
R51 "CRCW20101M00FKEF" 2010 1755,4440 r90 bottom value=1.00Meg
R52 "CRCW08052K00FKEA" 0805_HV 2235.08,4499.33 r0 bottom value=2.00k
R53 "CRCW120610R0FKEA" 1206 2892.56,1230.39 r90 bottom value=10.0
R54 "CRCW0603499KFKEA" 0603 1677.44,3679.96 r90 bottom value=499k
R55 "CRCW06034K70JNEA" 0603 2605,4280 r180 bottom value=4.7k
R56 "CRCW060310K0FKEA" 0603 6610,4685 r90 top value=10.0k
R57 "CRCW080520K0FKEA" 0805_HV 2507.56,3864.96 r180 bottom value=20.0k
R58 "CRCW08050000Z0EA" 0805_HV 3948.78,4365 r180 bottom value=0
R59 "CRCW08050000Z0EA" 0805_HV 3220,4110 r180 top value=0
R60 "CRCW080513K0FKEA" 0805_HV 2918.78,4060 r0 bottom value=13.0k
R61 "CRCW08052K00FKEA" 0805_HV 5390,4155 r0 bottom value=2.00k
R62 "CRCW08051K24FKEA" 0805_HV 5535,4095 r90 bottom value=1.24k
R63 "CRCW08051K00FKEA" 0805_HV 3095,3690 r180 top value=1.00k
R64 "CRCW080549R9FKEA" 0805_HV 6270,4120 r90 bottom value=49.9
R65 "CRCW080510K2FKEA" 0805_HV 2710,3810 r270 bottom value=10.2k
R66 "CRCW120610K0FKEA" 1206 3973.78,4510 r0 top value=10.0k
R67 "CRM2010-FX-R910ELF" 2010 2965,5282.04 r0 top value=0.91
R68 "CRM2010-FX-R910ELF" 2010 2965,5129.27 r0 top value=0.91
R69 "CRCW080512K4FKEA" 0805_HV 5910,4035 r270 bottom value=12.4k
R70 "CRCW08056K80JNEA" 0805_HV 5680,4265 r0 bottom value=6.8k
R71 "CRCW08059K09FKEA" 0805_HV 2787.56,3824.96 r90 top value=9.09k
R72 "CRCW08052K20JNEA" 0805_HV 2782.56,4024.96 r90 bottom value=2.2k
R73 "CRCW08052K43FKEA" 0805_HV 6015,4265 r180 bottom value=2.43k
R74 "CRCW08054K99FKEA" 0805_HV 2763.78,3595 r0 top value=4.99k
R75 "CRCW08051K00FKEA" 0805_HV 4025,3700 r270 bottom value=1.00k
R76 "CRCW08051K00FKEA" 0805_HV 2465,855 r90 top value=1.00k
R77 "CRCW08050000Z0EA" 0805_HV 2665,245.43 r0 top value=0
R78 "CRCW08053K16FKEA" 0805_HV 2454.41,360 r90 bottom value=3.16k
R79 "CRCW1206100RFKEA" 1206 6627.52,6262.44 r0 top value=100
R80 "CRCW120610R0FKEA" 1206 2895,4685 r90 bottom value=10.0
R81 "CRCW08050000Z0EA" 0805_HV 2517.56,3764.96 r0 bottom value=0
R82 "CRCW080540K2FKEA" 0805_HV 5830.31,3899.37 r0 bottom value=40.2k
R83 "CRCW08052K05FKEA" 0805_HV 5390,4050 r180 bottom value=2.05k
R84 "CRCW08051K00FKEA" 0805_HV 2870,535 r270 top value=1.00k
R85 "CRCW0805374RFKEA" 0805_HV 2350,3660 r180 top value=374
R86 "CRCW20101K50FKEF" 2010 3620,4300 r0 bottom value=1.50k
R87 "CRCW08053K01FKEA" 0805_HV 3360,4065 r90 top value=3.01k
R88 "CRCW0805100RFKEA" 0805_HV 4130,4240 r0 bottom value=100
R89 "CRCW20102R00FKEF" 2010 4180,4605 r90 bottom value=2.00
R90 "CRCW1206100RFKEA" 1206 3063.78,1625.39 r90 bottom value=100
R91 "CRCW1206100RFKEA" 1206 3053.78,5089.96 r90 bottom value=100
R92 "CRCW20101K50FKEF" 2010 3670,4005 r180 bottom value=1.50k
R93 "CRCW080537R4FKEA" 0805_HV 2310,3785 r270 top value=37.4
R94 "CRCW0805499RFKEA" 0805_HV 3865,3915 r90 bottom value=499
R95 "CRCW120610R0FKEA" 1206 4095,4050 r0 top value=10.0
R96 "CRCW0805237RFKEA" 0805_HV 3258.78,3965 r0 bottom value=237
R97 "CRCW0805470RFKEA" 0805_HV 3865,4075 r270 bottom value=470
R98 "CRCW12064R70JNEA" 1206 3809.37,4167.26 r0 top value=4.7
R99 "CRCW0805374RFKEA" 0805_HV 2340,495 r0 top value=374
R100 "CRCW080537R4FKEA" 0805_HV 2375,610 r270 top value=37.4
T1 "WA8759-AL" Coilcraft_WA8537-BL 4580,2620.43 r0 top value=1.5mH
T2 "WA8759-AL" Coilcraft_WA8537-BL 4576.85,6084.72 r0 top value=1.5mH
TP1 "5005" Keystone5005 3475,3095 r0 top
TP2 "5122" Keystone5122 215,1470 r0 top value=Blue
TP3 "5005" Keystone5005 7550,1680 r0 top
TP4 "5005" Keystone5005 2140,510 r0 top
TP6 "5122" Keystone5122 2145,275 r0 top value=Blue
TP7 "5006" Keystone5006 6610,185 r0 top
TP8 "5006" Keystone5006 3695,165 r0 top
TP9 "5005" Keystone5005 3340,6540 r0 top
TP10 "5122" Keystone5122 585,4005 r0 top value=Blue
TP11 "5005" Keystone5005 7575,5065 r0 top
TP14 "5005" Keystone5005 6730,4200 r0 top
TP15 "5122" Keystone5122 6380,3900 r0 top value=Blue
TP16 "5006" Keystone5006 7165,3630 r0 top
U1 "UCC28C43QDRQ1" D0008A_N 2995,441.65 r0 bottom
U2 "UCC28C43QDRQ1" D0008A_N 2995.08,3906.22 r0 bottom
U3 "FOD817ASD" N04C 5165,3900 r180 bottom
U4 "TL431AQDBZRQ1" DBZ0003A_N 5670,4010 r270 bottom
ZZ1 "This Assembly Note is for PCB labels only" AssemblyNoteLabel 1915,7465 r0 top
ZZ2 "These assemblies are ESD sensitive, ESD precautions shall be observed." AssemblyNote 1910,7375 r0 top
ZZ3 "These assemblies must be clean and free from flux and all contaminants. Use of no clean flux is not acceptable." AssemblyNote 1895,7270 r0 top
ZZ4 "These assemblies must comply with workmanship standards IPC-A-610 Class 2, unless otherwise specified." AssemblyNote 1900,7185 r0 top

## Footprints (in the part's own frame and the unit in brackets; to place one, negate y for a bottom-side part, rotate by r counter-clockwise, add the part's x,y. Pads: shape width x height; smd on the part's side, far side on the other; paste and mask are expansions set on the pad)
0603 [mm] "0603 from SM-752 data"
  rect 1x0.95 smd: 1(-0.8,0) 2(0.8,0)
  silkscreen extent -1.52,-0.69 1.52,0.69, body extent -0.87,-0.47 0.87,0.47, height 1
0805_HV [mil] "0805 with 30mil clearance between pads"
  rect 50x63 smd: 1(-40,0) 2(40,0)
  silkscreen extent -74,-40 74,40, body extent -43,-29 43,29, height 57
1206 [mm] "1206 from SM-752 data"
  rect 1.3x1.85 smd: 1(-1.45,0) 2(1.45,0)
  silkscreen extent -2.4,-1.21 2.4,1.21, body extent -1.7,-0.9 1.7,0.9, height 1.35
1206_180 [mm] "1206_180"
  rect 1.1x1.6 smd: 1(-1.7,0) 2(1.7,0)
  silkscreen extent -0.9,-1 0.9,1, body extent -1.75,-0.95 1.75,0.95, height 1.8
2010 [mm] "Chip Capacitor, Body 5.08x2.54mm, IPC Medium Density"
  rect 1.6x2.7 smd: 1(-2.3,0) 2(2.3,0)
  silkscreen extent -3.42,-1.65 3.42,1.65, body extent -2.73,-1.45 2.73,1.45, height 1.66
Aavid_7109DG [mm] "Surface mount heat sink for D2PAK"
  rect 5x5 smd: 1(0,0)
  Top Layer region: -8.38,-10.16 -8.38,10.16 8.38,10.16 8.38,-10.16 5.335,-10.16 5.335,-7.62 -5.335,-7.62 -5.335,-10.16
  silkscreen extent -12.7,-9.69 12.7,9.69, body extent -12.7,-9.69 12.7,9.69, height 12.03
AssemblyNote [mil] "Assembly Note"
AssemblyNoteLabel [mil] "Assembly Note for PCB Labels"
B32776P_4200x1800x3250 [mm] "TH, 2-Leads, Body 42x18mm, Pin Spacing 37.5mm"
  round 1.875 hole 1.25: 1(-18.75,0) 2(18.75,0)
  silkscreen extent -21,-9 21,9, body extent -21,-9 21,9, height 32.5
Chemi-Con_1000x2000 [mm] "TH, 2-Leads, Body 10x20mm, Pin Spacing 5mm"
  rect 1.35x1.35 hole 0.85: 1(-2.5,0)
  round 1.35 hole 0.85: 2(2.5,0)
  silkscreen extent -5.25,-5.25 5.25,5.25, body extent -5.25,-5.25 5.25,5.25, height 21.5
CK45-RR_1650x600 [mm] "TH, 2-Leads, Body 16.5x6mm"
  round 1.35 hole 0.9: 1(-5,0) 2(5,0)
  silkscreen extent -8.25,-3 8.25,3, body extent -8.25,-3 8.24,3, height 20.5
Coilcraft_WA8537-BL [mm] "SMD, 12-Leads, Body 38.3x31.9mm, Pitch 4.5mm"
  rrect6% 3x1.6 smd: 1(-17.9,11.25) 2(-17.9,6.75) 3(-17.9,2.25) 4(-17.9,-2.25) 5(-17.9,-6.75) 6(-17.9,-11.25) 7(17.9,-11.25) 8(17.9,-6.75) 9(17.9,-2.25) 10(17.9,2.25) 11(17.9,6.75) 12(17.9,11.25)
  silkscreen extent -20.2,-20.2 20.3,20.3, body extent -20,-20 20,20, height 13.6
CONN_PPTC021LFBN-RC [mil] "SULLINS"
  rect 62x62 hole 40: 1(50,0)
  round 62 hole 40.16: 2(-50,0)
  silkscreen extent -111,-51 111,97, body extent -110,-50 110,50, height 336
D0008A_N [mm] "SOIC, 8-Leads, Body 4.9x3.9mm, Pitch 1.27mm, IPC Medium Density"
  oval 1.45x0.6 smd: 1(-2.725,1.905) 2(-2.725,0.635) 3(-2.725,-0.635) 4(-2.725,-1.905) 5(2.725,-1.905) 6(2.725,-0.635) 7(2.725,0.635) 8(2.725,1.905)
  silkscreen extent -3.3,-2.5 0.9,2.5, body extent -3,-2.45 3,2.45, height 1.63
DBZ0003A_N [mm] "SOT23, 3-Leads, Body 2.9x1.3mm, Pitch 0.95mm, Lead Span 2.4mm, IPC Medium Density"
  rrect17% 1x0.6 smd: 1(-1.2,0.95) 2(-1.2,-0.95) 3(1.2,0)
  silkscreen extent 0.2,-1.5 0.7,1.5, body extent -1.26,-1.46 1.26,1.46, height 0.98
DDPAK [mil] "D2-PAK, 3-Pads, Body 9.7x10.4mm (max), TO-263AB, using Vishay Silionix recommended pad sizes"
  rrect8% 135x49.49 smd: 1(-246.06,100) 3(-246.06,-100)
  rrect1% 355x420 smd paste-181.1: 4(155.51,0)
  silkscreen extent -295,-220 344,220, body extent -295,-202 324,202, height 180
Fiducial10-20 [mm]
  round 1 smd mask+0.5: 1(0,0)
  Top Layer keep-out circle w1.178: c0,0 r0.5
HSINK_RA-T2X-25E [mm] "TH, 2-Leads, Body 42x25mm, Pin Spacing 25.4mm"
  round 3.83 hole 2.55: 1(-12.7,0) 2(12.7,0)
  silkscreen extent -21.25,-12.5 21.25,12.5, body extent -21.25,-12.5 21.25,12.5, height 25.4
IEC_HighVoltage_Medium [mil]
  silkscreen extent -217,-176 217,200
Kemet_3200x1800x3300 [mm] "TH, 2-Leads, Body 32x18mm, Pin Spacing 27.5mm"
  round 1.65 hole 1.1: 1(-13.75,0) 2(13.75,0)
  silkscreen extent -16.15,-9.1 16.15,9.1, body extent -16.15,-9.1 16.15,9.1, height 33.1
Keystone5005 [mil] "Keystone Compact loops"
  round 87 hole 63: 1(0,0)
  silkscreen extent -70,-70 70,70, body extent -63,-63 62,63, height 225
Keystone5006 [mil] "Keystone Compact loops"
  round 87 hole 63: 1(0,0)
  silkscreen extent -70,-70 70,70, body extent -63,-63 62,63, height 225
Keystone5122 [mil] "Keystone Compact loops"
  round 87 hole 63: 1(0,0)
  silkscreen extent -70,-70 70,70, body extent -63,-63 62,63, height 225
Keystone_1902C [mil] "Hex Standoff, 4-40 threaded, nylon"
  round 1 on Mech4: 0(0,0)
  body extent -145,-126 146,126, height 501
N04C [mm] "FAIRCHILD"
  rect 1.3x1.5 smd mask+0.065: 1(-4.587,1.27) 2(-4.612,-1.27) 3(4.588,-1.27) 4(4.613,1.27)
  silkscreen extent -3.56,-2.3 3.56,2.72, body extent -5.08,-2.3 5.08,2.29, height 3.87
"NY PMS 440 0025 PH" [mm] "4-40 nylon screw and mounting hole"
  round 8 hole 3.2: 1(0,0)
  body extent -3.3,-3.3 3.3,3.3, height 2.69
Pb-Free_Overlay_Small [mil]
  silkscreen extent -46,-46 46,46
PhoenixContact_1715721 [mm] "Phoenix Contact 1715721 used on LM3445 design from Longmont"
  rrect5% 1.905x1.905 hole 1.3: 1(-2.54,0)
  round 1.9 hole 1.3: 2(2.54,0)
  silkscreen extent -5.82,-5.25 5.08,5.2, body extent -5.82,-4.6 5.08,5.2, height 14.2
PowerDI123 [mm] "Diodes Inc recommended land pattern, document number DS30628 Rev. 6-2"
  rect 2.2x1.4 smd: 1(-1.275,0)
  rect 0.9x1.4 smd: 2(1.275,0)
  silkscreen extent -3.1,-1.09 1.76,1.09, body extent -2.37,-0.96 1.53,0.97, height 1
Samtec_HTSW-103-09-x-S [mm] "Header, 3x1, 2.54mm, TH"
  rect 1.55x1.55 hole 1.02: 1(-2.54,0)
  round 1.55 hole 1.02: 2(0,0) 3(2.54,0)
  silkscreen extent -3.81,-1.24 3.81,1.5, body extent -3.81,-1.24 3.81,1.24, height 8.38
SM_RADIAL_D [mm] "6.3 x 5.8mm:  Panasonic D"
  rect 3.2x1.6 smd: 1(-2.5,0) 2(2.5,0)
  silkscreen extent -3.4,-3.4 3.4,3.4, body extent -3.4,-3.4 3.4,3.4, height 6.1
SM_RADIAL_E [mm] "8 x 6.2mm:  Panasonic E"
  rect 4x1.6 smd: 1(-3.1,0) 2(3.1,0)
  silkscreen extent -4.25,-4.25 4.25,4.25, body extent -4.25,-4.25 4.25,4.25, height 6.5
SMA [mm] "Molded Diode, 2-Leads, Body 4.3x2.6mm, IPC Medium Density, based on OnSemi component dimensions and land pattern"
  rect 2x2 smd: 1(-2,0) 2(2,0)
  silkscreen extent -3.66,-1.57 2.79,1.57, body extent -2.6,-1.3 2.6,1.3, height 2.42
SMB [mil] "Molded Diode, 2-Leads, Body 5.4x3.6mm, IPC Medium Density, based on OnSemi component dimensions"
  rect 85x107.99 smd: 1(-87.01,0) 2(87.01,0)
  silkscreen extent -155,-82 125,82, body extent -106,-71 106,71, height 91
SMC_265 [mm] "SMD, 2-Leads, Body 7.15x6.25mm"
  rect 2.6x3.2 smd: 1(-3.6,0) 2(3.6,0)
  silkscreen extent -5.6,-3.22 5.3,3.22, body extent -4.08,-3.13 4.08,3.13, height 2.65
SOD-123 [mm] "On Semi recommended land pattern"
  rect 0.915x1.22 smd: 1(-1.637,0) 2(1.637,0)
  silkscreen extent -2.74,-1.17 2.03,1.17, body extent -1.93,-0.9 1.93,0.9, height 1.35
SOD-923 [mm] "ON-SEMI"
  rect 0.36x0.25 smd: 1(-0.42,0) 2(0.42,0)
  silkscreen extent -1.02,-0.38 -0.76,0.38, body extent -0.45,-0.35 0.45,0.35, height 0.44
SOT-23 [mm] "SOT23, 3-Leads, Body 2.9x1.3mm, Pitch 0.95mm, Lead Span 2.5mm, IPC Medium Density"
  rrect50% 1x0.6 smd: 1(-1.2,0.95) 2(-1.2,-0.95) 3(1.2,0)
  silkscreen extent -1.62,-1.5 0.7,1.5, body extent -1.16,-1.45 1.21,1.45, height 1
SOT-89-3 [mm] "SOT, 3-Leads, Body 4.6 x 2.6 mm, Pitch 1.5mm"
  rect 1.4x0.9 smd: 1(-1.9,1.5) 3(-1.9,-1.5)
  rect 1.8x0.9 smd: 2(-1.7,0)
  oct 3.4x1.9 smd: 4(0.9,0)
  silkscreen extent -1.3,-2.45 1.33,2.45, body extent -2.42,-2.28 1.83,2.32, height 1.62
TO-220AB [mil] "Copied from Altium's version of TO3B"
  rrect25% 76x118.11 hole 50: 1(-100,0)
  oval 76x118.11 hole 50: 2(0,0) 3(100,0)
  silkscreen extent -221,-59 221,126, body extent -221,-59 221,126, height 765
TO-247 [mil] "Standard TO-247"
  rrect50% 95x95 hole 62: 1(-215,0)
  round 95 / inner round 74.8 / far side round 96 hole 62: 2(0,0) 3(215,0)
  silkscreen extent -318,-124 318,81, body extent -318,-124 318,81, height 1007
WL-SMCW_GREEN [mm] "WURTH"
  rect 0.8x0.8 smd: 1(-0.8,0) 2(0.8,0)
  silkscreen extent -1.9,-0.8 1.2,0.8, body extent -0.85,-0.45 0.85,0.45, height 0.8
XAL6030 [mil] "Coilcraft recommended land pattern Document 887-4 Revised 11/20/12"
  rect 56x224 smd: 1(-79.5,0) 2(79.5,0)
  silkscreen extent -129,-133 129,133, body extent -129,-133 129,133, height 122

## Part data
C1 C2 C36 C37: library part CMP-0074791-1, "CAP, CERM, 2200 pF, 3000 V,+/- 10%, ?, 16.5x6mm", Cap_Case=16.5x6mm, Manufacturer=TDK, Supplier Part Number 1=445-16032-ND, TempCo=R, Tolerance_%=10%, Value2=3000V, ValueDisplayed=2200pF
C3 C6 C7 C38 C41 C47: library part CMP-0074803-1, "CAP, Film, 10 μF, 630 V,+/- 10%, 0.007 ohm, AEC-Q200 Grade 1, TH", Cap_Case=42x18x32.5mm, Manufacturer=TDK, Supplier Part Number 1=495-75565-ND, Tolerance_%=10%, Value1="0.007 ohm", Value2=630V, ValueDisplayed=10μF
C4 C40 C72 C75: "CAP, CERM, 1000 pF, 630 V,+/- 5%, C0G/NP0, 1206", Cap_Case=1206, Manufacturer=MuRata, Supplier Part Number 1=490-5279-1-ND, TempCo=C0G/NP0, Tolerance_%=5, Value2=630V, ValueDisplayed=1000pF
C5 C39: library part CMP-0077096-1, "CAP, Film, 0.22 μF, 1600 V,+/- 5%, AEC-Q200 Grade 2, TH", Cap_Case=32x18x33mm, Manufacturer=Kemet, Supplier Part Number 1=399-12848-ND, Tolerance_%=5%, Value2=1600V, ValueDisplayed=0.22μF
C8 C9 C17 C27 C51 C52: "CAP, AL, 470 μF, 35 V, +/- 20%, TH", Cap_Case=10x20, Manufacturer=Chemi-Con, Supplier Part Number 1=565-1694-ND, Tolerance_%=20, Value2=35V, ValueDisplayed=470μF
C10 C11 C13 C14 C15 C16 C24 C25 C34 C44 C45 C46 C48 C49 C50 C57 C58 C78 C81: "CAP, CERM, 10 μF, 35 V,+/- 10%, X5R, 0805", Cap_Case=0805, Manufacturer=MuRata, Supplier Part Number 1=490-10514-1-ND, TempCo=X5R, Tolerance_%=10, Value2=35V, ValueDisplayed=10μF
C12 C53 C68: "CAP, CERM, 0.22 μF, 50 V,+/- 10%, X7R, 0805", Cap_Case=0805, Manufacturer=MuRata, Supplier Part Number 1=490-1670-1-ND, TempCo=X7R, Tolerance_%=10, Value2=50V, ValueDisplayed=0.22μF
C18 C54: "CAP, AL, 22 μF, 50 V, +/- 20%, 0.88 ohm, AEC-Q200 Grade 2, SMD", Cap_Case=D, Manufacturer=Panasonic, Supplier Part Number 1=PCE3811CT-ND, Tolerance_%=20, Value1="0.88 ohm", Value2=50V, ValueDisplayed=22μF
C19 C26 C28 C55 C59 C63: "CAP, CERM, 0.1 μF, 50 V,+/- 10%, X7R, 0805", Cap_Case=0805, Manufacturer=TDK, Supplier Part Number 1=445-7534-1-ND, TempCo=X7R, Tolerance_%=10, Value1="0.02619 ohm", Value2=50V, ValueDisplayed=0.1μF
C20 C56: "CAP, CERM, 2.2 μF, 50 V,+/- 10%, X7R, AEC-Q200 Grade 1, 0805", Cap_Case=0805, Manufacturer=TDK, Supplier Part Number 1=445-174216-1-ND, TempCo=X7R, Tolerance_%=10, Value1="0.003288 ohm", Value2=50V, ValueDisplayed=2.2μF
C21 C42 C60 C69 C80: "CAP, CERM, 1 μF, 100 V,+/- 10%, X7R, 1206", Cap_Case=1206, Manufacturer=MuRata, Supplier Part Number 1=490-3909-1-ND, TempCo=X7R, Tolerance_%=10, Value2=100V, ValueDisplayed=1μF
C22 C23 C61 C62: "CAP, CERM, 1 μF, 25 V,+/- 10%, X7R, 0805", Cap_Case=0805, Manufacturer=MuRata, Supplier Part Number 1=GRM21BR71E105KA99L-ND, TempCo=X7R, Tolerance_%=10, Value2=25V, ValueDisplayed=1μF
C29 C64: "CAP, CERM, 1 μF, 25 V,+/- 10%, X7R, 0603", Cap_Case=0603, Manufacturer=MuRata, Supplier Part Number 1=490-5307-1-ND, TempCo=X7R, Tolerance_%=10, Value2=25V, ValueDisplayed=1μF
C30: "CAP, CERM, 0.33 μF, 25 V,+/- 10%, X7R, 0805", Cap_Case=0805, Manufacturer=MuRata, Supplier Part Number 1=490-1677-1-ND, TempCo=X7R, Tolerance_%=10, Value2=25V, ValueDisplayed=0.33μF
C31 C65: "CAP, CERM, 1000 pF, 50 V,+/- 5%, C0G/NP0, AEC-Q200 Grade 1, 0805", Cap_Case=0805, Manufacturer=MuRata, Supplier Part Number 1=490-8032-1-ND, TempCo=C0G/NP0, Tolerance_%=5, Value2=50V, ValueDisplayed=1000pF
C32: "CAP, CERM, 560 pF, 25 V,+/- 10%, X7R, 0805", Cap_Case=0805, Manufacturer=MuRata, Supplier Part Number 1=GRM216R71E561KA01D-ND, TempCo=X7R, Tolerance_%=10, Value2=25V, ValueDisplayed=560pF
C33 C67: "CAP, CERM, 0.01 μF, 50 V,+/- 10%, X7R, 0805", Cap_Case=0805, Manufacturer=MuRata, Supplier Part Number 1=490-1664-1-ND, TempCo=X7R, Tolerance_%=10, Value2=50V, ValueDisplayed=0.01μF
C35 C70: "CAP, CERM, 220 pF, 50 V,+/- 5%, C0G/NP0, 0805", Cap_Case=0805, Manufacturer=MuRata, Supplier Part Number 1=490-1616-1-ND, TempCo=C0G/NP0, Tolerance_%=5, Value2=50V, ValueDisplayed=220pF
C43: "CAP, CERM, 0.01 μF, 100 V,+/- 10%, X7R, 0805", Cap_Case=0805, Manufacturer=MuRata, Supplier Part Number 1=490-1652-1-ND, TempCo=X7R, Tolerance_%=10, Value2=100V, ValueDisplayed=0.01μF
C66: "CAP, CERM, 3300 pF, 50 V,+/- 5%, C0G/NP0, 0805", Cap_Case=0805, Manufacturer=MuRata, Supplier Part Number 1=490-1632-1-ND, TempCo=C0G/NP0, Tolerance_%=5, Value2=50V, ValueDisplayed=3300pF
C71: "CAP, CERM, 0.33 μF, 50 V,+/- 10%, X7R, 0805", Cap_Case=0805, Manufacturer=MuRata, Supplier Part Number 1=490-3327-1-ND, TempCo=X7R, Tolerance_%=10, Value2=50V, ValueDisplayed=0.33μF
C73 C76: "CAP, AL, 10 μF, 100 V, +/- 20%, AEC-Q200 Grade 3, SMD", Cap_Case=8.0x6.0mm, Manufacturer=Panasonic, Supplier Part Number 1=PCE3966CT-ND, Tolerance_%=20, Value2=100V, ValueDisplayed=10μF
C74: "CAP, CERM, 620 pF, 100 V,+/- 5%, C0G/NP0, 0805", Cap_Case=0805, Manufacturer=MuRata, Supplier Part Number 1=GRM2165C2A621JA01D-ND, TempCo=C0G/NP0, Tolerance_%=5, Value2=100V, ValueDisplayed=620pF
C77: "CAP, CERM, 0.1 μF, 50 V,+/- 10%, X7R, AEC-Q200 Grade 1, 0805", Cap_Case=0805, Manufacturer=MuRata, Supplier Part Number 1=490-8049-1-ND, TempCo=X7R, Tolerance_%=10, Value2=50V, ValueDisplayed=0.1μF
C79: "CAP, CERM, 100 pF, 50 V,+/- 5%, C0G/NP0, 0603", Cap_Case=0603, Manufacturer=MuRata, Supplier Part Number 1=490-1427-1-ND, TempCo=C0G/NP0, Tolerance_%=5, Value2=50V, ValueDisplayed=100pF
C82 C83: "CAP, CERM, 150 pF, 50 V,+/- 5%, C0G/NP0, 0805", Cap_Case=0805, Manufacturer=MuRata, Supplier Part Number 1=490-3315-1-ND, TempCo=C0G/NP0, Tolerance_%=5, Value2=50V, ValueDisplayed=150pF
D1 D2 D3 D17 D18 D20: "Diode, TVS, Uni, 110 V, SMC", Manufacturer=Littelfuse, Power_W=6.5, Supplier Part Number 1=SMCJ110ALFCT-ND, Value1=6.5W
D4 D25: "Diode, Schottky, 150 V, 10 A, DDPAK", Manufacturer=Vishay-Semiconductor, Supplier Part Number 1=VS-20CTQ150SPBFGI-ND, Value1=10A, Value2=0.66V
D5 D6 D21 D22: "Diode, Ultrafast, 1000 V, 1 A, SMA", Manufacturer="Diodes Inc.", Supplier Part Number 1=US1M-FDICT-ND, Value1=1A, Value2=1.7V
D7 D9 D16 D23 D33 D34: library part CMP-0074851-1, "Diode, Fast Rectifier, 300 V, 1 A, SMA", Manufacturer="Fairchild Semiconductor", Supplier Part Number 1=ES1FCT-ND, Value1=1A, Value2=1.3V
D8 D24: "Diode, Zener, 18 V, 500 mW, SOD-123", Manufacturer="ON Semiconductor", Power_W=0.5, Supplier Part Number 1=MMSZ4705T1GOSCT-ND, Value1=0.5W
D10: "Diode, Zener, 18 V, 1 W, PowerDI123", Manufacturer="Diodes Inc.", Power_W=1, Supplier Part Number 1=DFLZ18DICT-ND, Value1=1W
D11 D27: library part CMP-0005755-2, "Diode, Zener, 18 V, 500 mW, SOD-123", Manufacturer="Diodes Inc.", Power_W=500mW, Supplier Part Number 1=MMSZ5248B-FDICT-ND, Value1=0.5W
D12 D28: library part CMP-0002905-1, "LED, Green, SMD", Color=Green, Manufacturer="Wurth Elektronik", Supplier Part Number 1=732-4971-1-ND, Value1=W, Value2=3.2V
D13 D29: "Diode, Schottky, 60 V, 0.1 A, SOD-923", Manufacturer=Rohm, Supplier Part Number 1=RB520CM-60T2RCT-ND, Value1=0.1A, Value2=V
D14 D30: "Diode, Zener, 22 V, 500 mW, SOD-123", Manufacturer="Diodes Inc.", Power_W=0.5, Supplier Part Number 1=MMSZ5251B-FDICT-ND, Value1=0.5W
D15 D36: "Diode, Schottky, 70 V, 1 A, SMA", Manufacturer="Diodes Inc.", Supplier Part Number 1=B170-FDICT-ND, Value1=1A, Value2=0.79V
D19 D35: library part CMP-0005551-2, "Diode, TVS, Uni, 18 V, 29.2 Vc, SMB", Manufacturer="Diodes Inc.", Power_W=5W, Supplier Part Number 1=SMBJ18A-FDICT-ND
D26: "Diode, Zener, 16 V, 1 W, PowerDI123", Manufacturer="Diodes Inc.", Power_W=1, Supplier Part Number 1=DFLZ16DICT-ND, Value1=1W
D31: library part CMP-0005766-2, "Diode, Zener, 11 V, 500 mW, SOD-123", Manufacturer="Diodes Inc.", Power_W=500mW, Supplier Part Number 1=BZT52C11-FDICT-ND, Value1=0.5W
D32: "Diode, Zener, 5.6 V, 500 mW, SOD-123", Manufacturer="Diodes Inc.", Power_W=0.5, Supplier Part Number 1=MMSZ5232B-FDICT-ND, Value1=0.5W
FID1 FID2 FID3 FID4 FID5 FID6: "Fiducial mark.  There is nothing to buy or mount.", Manufacturer=N/A
H1 H2 H3 H4 H11 H15 H17 H18: "Machine Screw, Round, #4-40 x 1/4, Nylon, Philips panhead", DigiKeyPartNumber=H542-ND, Manufacturer="B&F Fastener Supply"
H5 H6 H7 H8 H12 H16 H19 H20: "Standoff, Hex, 0.5\"L #4-40 Nylon", Alternate Manufacturer=-, Manufacturer=Keystone, Supplier Part Number 1=1902CK-ND
H9 H10: library part CMP-0004038-1, "Surface mount heat sink for D2PAK", Manufacturer=Aavid, Supplier Part Number 1=HS406-ND
H13 H14: library part CMP-0076741-1, "Heatsink, TO-220, TO-218, TO-247", Manufacturer=Ohmite, Supplier Part Number 1=RA-T2X-25E-ND
J1 J3 J4 J6 J7 J10 J11 J12 J13: library part CMP-0055471-1, "Terminal Block, 5.08 mm, 2x1, TH", Color=Green, Current_A=17.5A, Manufacturer="Phoenix Contact", Supplier Part Number 1=277-1263-ND, Voltage_V=400V
J2 J5 J8 J9: library part CMP-0054631-1, "Receptacle, 100mil, 2x1, Tin, TH", Color=Black, Current_A=3A, Manufacturer="Sullins Connector Solutions", Supplier Part Number 1=S7000-ND, Voltage_V=250V
J14: "Header, 100mil, 3x1, Gold, TH", Color=Black, Manufacturer=Samtec
L1 L2: "Inductor, Shielded, Composite, 2.2 μH, 12.7 A, 0.012 ohm, SMD", Manufacturer=Coilcraft, Value1="0.012 ohm", Value2=12.7A, ValueDisplayed=2.2μH
Logo2: library part Pb-Free
LOGO4 LOGO5 LOGO6 LOGO7: library part IEC_HighVoltage, "IEC 61010-1 High Voltage Warning"
Q1 Q9: library part CMP-0074796-1, "Transistor, NPN, 1200 V, .1 A, TO-220AB", Manufacturer=STMicroelectronics, Supplier Part Number 1=497-7022-5-ND, Value1=".1 A"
